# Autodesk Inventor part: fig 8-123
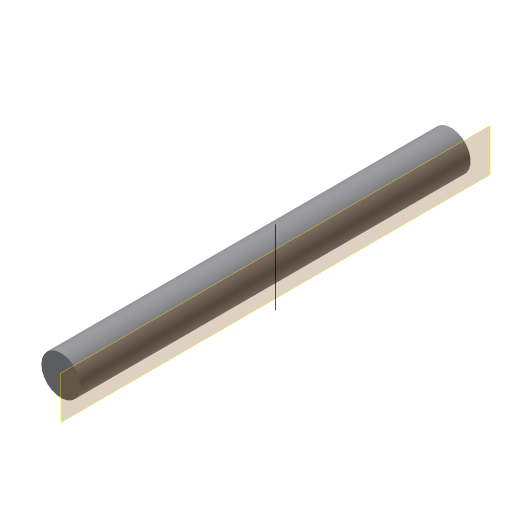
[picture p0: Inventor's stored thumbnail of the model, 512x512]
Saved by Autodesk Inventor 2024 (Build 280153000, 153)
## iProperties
Created: 2007-02
Part Number: fig 8-123
Document SubType Name: Modeling
Designer: Administrator
Density: 1 g/cm^3
Material: Generic
Appearance: Default
Author: Administrator
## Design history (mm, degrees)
sketch "Sketch2"
  geometry: C1 r 5 at (0, 0); 1 further point
  constraints: 1 centre point, 1 coincident, 1 other
  dimensions: "d0" = 10 diameter of C1
extrude "Extrusion1" new body sketch "Sketch2" stored distance "d1" = 100; taper "d2" = 0 deg
workplane "Work Plane1"
sketch "Sketch3"
  geometry: L1 (0, 11)-(0, -8)
  constraints: 2 end point, 1 vertical
body "Solid1"
node "Sketch1"
